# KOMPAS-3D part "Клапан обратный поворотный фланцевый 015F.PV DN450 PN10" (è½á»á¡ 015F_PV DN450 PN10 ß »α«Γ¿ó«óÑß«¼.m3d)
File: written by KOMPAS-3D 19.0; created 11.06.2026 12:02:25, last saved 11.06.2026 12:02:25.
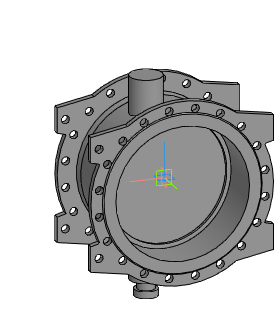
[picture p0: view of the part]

Document properties: Автор: Энергия; Полное имя файла: Z:\3.Личные\kachalov\001_3d для проектировщиков\5.5 Тип 015F.PV Клапан обратный поворотный с двумя эксцентриками\_stp_Клапан 015F.PV DN300-DN1200 с противовесом\Клапан 015F_PV DN450 PN10 с противовесом.m3d

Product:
- Part/product: Клапан обратный поворотный фланцевый 015F.PV DN450 PN10

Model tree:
1. Операция без истории:1
2. Сплайн:1
     Координата Y = 30; Координата Z = 225; Вес = 1; Координата X = 450; Координата Y = 89.2436; Координата Z = 225; Вес = 0.333333; Координата X = 450; Координата Y = 89.2436; Координата Z = -225; Вес = 0.333333; Координата Y = 30; Координата Z = -225; Вес = 1; Координата X = -450; Координата Y = -29.2436; Координата Z = -225; Вес = 0.333333; Координата X = -450; Координата Y = -29.2436; Координата Z = 225; Вес = 0.333333; Порядок = 4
